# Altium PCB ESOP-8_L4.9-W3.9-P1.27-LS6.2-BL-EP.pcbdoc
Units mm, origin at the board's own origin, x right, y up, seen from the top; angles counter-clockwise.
Board outline 17.8 x 19.91 mm, 2 copper layers (Top Layer, Bottom Layer), stack 0 mm thick; 1 components, 0 nets, 9 pads, 0 vias.
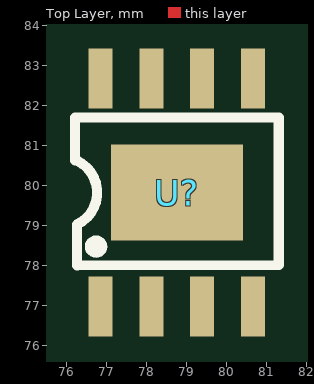
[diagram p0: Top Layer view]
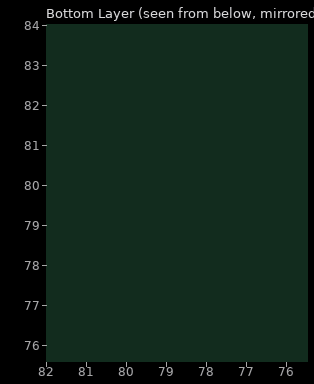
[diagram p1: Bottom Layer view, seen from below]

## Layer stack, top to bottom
Top Layer: signal copper (thickness not stored)
Bottom Layer: signal copper (thickness not stored)

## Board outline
87.65,69.85 69.85,69.85 69.85,89.76 87.65,89.76

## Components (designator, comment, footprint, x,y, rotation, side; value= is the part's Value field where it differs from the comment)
U? "" ESOP-8_L4.9-W3.9-P1.27-LS6.2-BL-EP 78.75,79.81 r0 top

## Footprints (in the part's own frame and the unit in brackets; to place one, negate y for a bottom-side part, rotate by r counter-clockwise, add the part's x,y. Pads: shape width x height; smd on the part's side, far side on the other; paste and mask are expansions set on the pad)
ESOP-8_L4.9-W3.9-P1.27-LS6.2-BL-EP [mm]
  rect 0.6x1.5 smd: 1(-1.905,-2.85) 2(-0.635,-2.85) 3(0.635,-2.85) 4(1.905,-2.85) 5(1.905,2.85) 6(0.635,2.85) 7(-0.635,2.85) 8(-1.905,2.85)
  rect 3.3x2.4 smd: 9(0,0)
  silkscreen extent -2.55,-1.82 2.55,1.88

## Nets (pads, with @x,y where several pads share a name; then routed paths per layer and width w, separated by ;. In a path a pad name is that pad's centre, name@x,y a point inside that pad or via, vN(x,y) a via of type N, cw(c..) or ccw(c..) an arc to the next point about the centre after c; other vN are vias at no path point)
pads on no net: U?.1 U?.2 U?.3 U?.4 U?.5 U?.6 U?.7 U?.8 U?.9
